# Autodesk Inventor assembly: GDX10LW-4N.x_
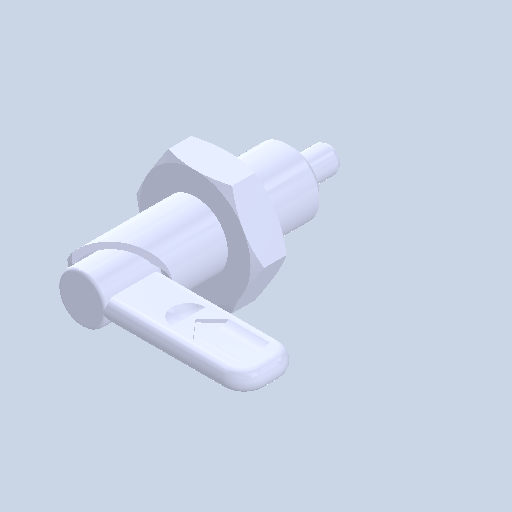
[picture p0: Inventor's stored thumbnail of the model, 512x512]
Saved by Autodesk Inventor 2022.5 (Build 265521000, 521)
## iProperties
Created: 2024-06
Part Number: GDX10LW-4N.x_
Document SubType Name: Assembly
Designer: ImaoCorp
Author: ImaoCorp
Sending System: SOLIDWORKS 2022-2022290
MC: AMD64
MC_MODEL: Intel64 Family 6 Model 60 Stepping 3, GenuineIntel
OS: Windows_NT
FRU: Parasolid Version 33.1, build 260,  4-25-2022
FORMAT: text
GUISE: transmit
KEY: FILEGDX10LW-4N.x_t
DATE: Wed Jun 12 09:31:24 2024
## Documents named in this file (4)
- Y:\5.更新分\2024年対応\xxxx_GDX\データ_imao品番\gdx10lw-4n\GDX10LW-4N.x_.iam
- Y:\5.更新分\2024年対応\xxxx_GDX\データ_imao品番\gdx10lw-4n\GDX10LW-4N_01.ipt
- Y:\5.更新分\2024年対応\xxxx_GDX\データ_imao品番\gdx10lw-4n\GDX10LW-4N_02.ipt
- Y:\5.更新分\2024年対応\xxxx_GDX\データ_imao品番\gdx10lw-4n\GDX10LW-4N_03.ipt
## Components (3 placed, 3 different names)
1. GDX10LW-4N_01
2. GDX10LW-4N_02
3. GDX10LW-4N_03
